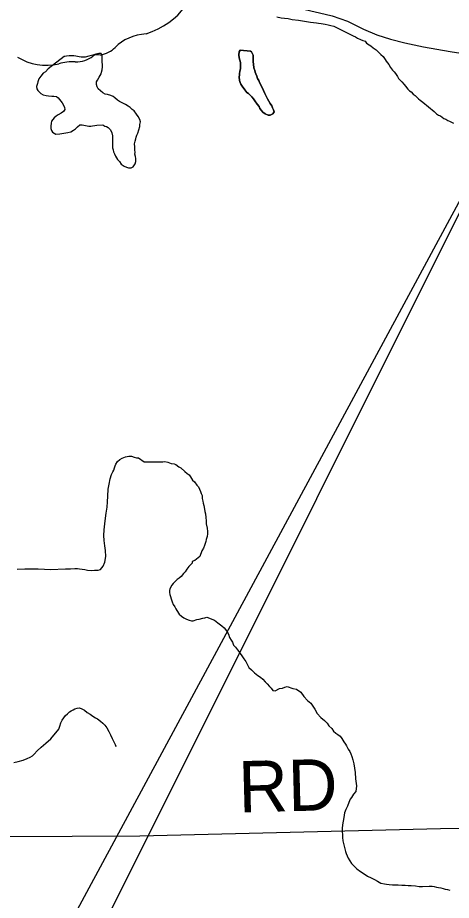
# Model space of a CAD drawing. Extents: x 0 to 34, y 0 to 22.
# Drawn here: x 6.066 to 6.547, y 16.147 to 17.124 of the extents above; entities that cross this region are included whole.
import ezdxf

# ---------------------------------------------------------------- set-up
doc = ezdxf.new("R2010")
doc.units = 0
for name, color, linetype in [('Default', 7, 'Continuous'), ('GM_X_Minor_Lake', 7, 'Continuous'), ('GM_X_Minor_River', 7, 'Continuous'), ('GM_X_State_Route', 7, 'Continuous'), ('GM_X_State_Shield', 7, 'Continuous'), ('GM_X_Township_Road', 7, 'Continuous'), ('GM_X_Township_Road_Text', 7, 'Continuous')]:
    doc.layers.add(name, color=color, linetype=linetype)

msp = doc.modelspace()

# ---------------------------------------------------------------- linework, layer by layer
at = {"layer": 'Default'}
msp.add_lwpolyline([(5.90994, 15.72564), (6.64074, 17.07843), (5.90994, 15.61811)], close=True, dxfattribs=at)
at = {"layer": 'GM_X_Minor_Lake'}
for points in [[(6.19735, 16.96793), (6.19699, 16.96984), (6.19626, 16.9725), (6.19629, 16.97441), (6.19594, 16.97745), (6.19598, 16.98049), (6.19564, 16.98392), (6.19644, 16.98695), (6.19723, 16.9896), (6.19763, 16.99149), (6.19842, 16.99339), (6.19958, 16.99565), (6.20157, 17.00323), (6.2016, 17.00551), (6.20239, 17.00816), (6.20167, 17.01083), (6.19981, 17.01428), (6.19794, 17.01696), (6.19532, 17.02041), (6.19306, 17.02196), (6.19081, 17.02427), (6.18854, 17.02581), (6.1859, 17.02737), (6.18363, 17.02853), (6.18137, 17.0297), (6.1791, 17.03087), (6.17684, 17.03242), (6.17382, 17.03473), (6.17194, 17.03627), (6.16968, 17.03744), (6.16589, 17.03863), (6.16323, 17.03904), (6.16058, 17.04021), (6.15795, 17.04252), (6.15532, 17.04484), (6.15421, 17.04713), (6.15347, 17.04942), (6.15351, 17.05246), (6.15467, 17.05434), (6.15662, 17.05774), (6.15778, 17.05963), (6.15894, 17.06152), (6.15934, 17.06341), (6.15975, 17.06569), (6.16017, 17.06911), (6.15989, 17.07671), (6.15992, 17.07937), (6.15994, 17.08165), (6.15883, 17.08395), (6.15617, 17.08398), (6.15274, 17.08326), (6.14968, 17.08215), (6.14511, 17.08107), (6.14092, 17.07998), (6.13673, 17.07965), (6.13446, 17.08005), (6.13256, 17.08046), (6.13066, 17.08086), (6.12839, 17.08127), (6.12649, 17.08129), (6.12345, 17.08133), (6.1204, 17.08098), (6.1185, 17.08062), (6.11774, 17.08063)], [(6.19735, 16.96793), (6.19699, 16.96984), (6.19626, 16.9725), (6.19629, 16.97441), (6.19594, 16.97745), (6.19598, 16.98049), (6.19564, 16.98392), (6.19644, 16.98695), (6.19723, 16.9896), (6.19763, 16.99149), (6.19842, 16.99339), (6.19958, 16.99565), (6.20157, 17.00323), (6.2016, 17.00551), (6.20239, 17.00816), (6.20167, 17.01083), (6.19981, 17.01428), (6.19794, 17.01696), (6.19532, 17.02041), (6.19306, 17.02196), (6.19081, 17.02427), (6.18854, 17.02581), (6.1859, 17.02737), (6.18363, 17.02853), (6.18137, 17.0297), (6.1791, 17.03087), (6.17684, 17.03242), (6.17382, 17.03473), (6.17194, 17.03627), (6.16968, 17.03744), (6.16589, 17.03863), (6.16323, 17.03904), (6.16058, 17.04021), (6.15795, 17.04252), (6.15532, 17.04484), (6.15421, 17.04713), (6.15347, 17.04942), (6.15351, 17.05246), (6.15467, 17.05434), (6.15662, 17.05774), (6.15778, 17.05963), (6.15894, 17.06152), (6.15934, 17.06341), (6.15975, 17.06569), (6.16017, 17.06911), (6.15989, 17.07671), (6.15992, 17.07937), (6.15994, 17.08165), (6.15883, 17.08395), (6.15617, 17.08398), (6.15274, 17.08326), (6.14968, 17.08215), (6.14511, 17.08107), (6.14092, 17.07998), (6.13673, 17.07965), (6.13446, 17.08005), (6.13256, 17.08046), (6.13066, 17.08086), (6.12839, 17.08127), (6.12649, 17.08129), (6.12345, 17.08133), (6.1204, 17.08098), (6.1185, 17.08062), (6.11774, 17.08063)], [(6.32428, 17.08648), (6.31277, 17.08764), (6.31161, 17.08575), (6.31122, 17.08233), (6.31163, 17.07912)], [(6.31163, 17.07912), (6.31122, 17.08233), (6.31161, 17.08575), (6.31277, 17.08764), (6.32428, 17.08648)], [(6.31163, 17.07912), (6.31308, 17.07395), (6.31306, 17.07129), (6.31304, 17.06748), (6.31226, 17.06406), (6.31187, 17.06178), (6.31186, 17.05988), (6.31147, 17.05798), (6.31183, 17.05418), (6.31258, 17.05189), (6.31333, 17.04998), (6.31484, 17.04769), (6.31787, 17.04387), (6.32014, 17.04081), (6.32204, 17.03966), (6.32393, 17.03774), (6.32583, 17.03583), (6.32734, 17.03391), (6.32885, 17.03162), (6.3315, 17.0278), (6.33377, 17.02512), (6.33452, 17.02322), (6.33604, 17.0213), (6.33793, 17.01901), (6.34059, 17.01709), (6.34363, 17.01555), (6.34591, 17.01553), (6.34897, 17.01703), (6.3505, 17.01931), (6.34975, 17.02159), (6.34862, 17.02388), (6.34787, 17.02617), (6.34598, 17.02847), (6.34447, 17.03114), (6.34296, 17.03381), (6.34145, 17.03686), (6.33994, 17.03954), (6.33844, 17.04297), (6.3358, 17.04907), (6.33429, 17.05175), (6.33354, 17.05403), (6.33203, 17.05632), (6.33128, 17.05899), (6.33015, 17.06128), (6.3294, 17.06319), (6.32903, 17.06509), (6.3279, 17.06814), (6.32754, 17.07195), (6.32717, 17.07461), (6.32719, 17.0769), (6.3272, 17.07918), (6.32722, 17.08222), (6.32533, 17.08566), (6.32428, 17.08648)], [(6.32428, 17.08648), (6.32533, 17.08566), (6.32722, 17.08222), (6.3272, 17.07918), (6.32719, 17.0769), (6.32717, 17.07461), (6.32754, 17.07195), (6.3279, 17.06814), (6.32903, 17.06509), (6.3294, 17.06319), (6.33015, 17.06128), (6.33128, 17.05899), (6.33203, 17.05632), (6.33354, 17.05403), (6.33429, 17.05175), (6.3358, 17.04907), (6.33844, 17.04297), (6.33994, 17.03954), (6.34145, 17.03686), (6.34296, 17.03381), (6.34447, 17.03114), (6.34598, 17.02847), (6.34787, 17.02617), (6.34862, 17.02388), (6.34975, 17.02159), (6.3505, 17.01931), (6.34897, 17.01703), (6.34591, 17.01553), (6.34363, 17.01555), (6.34059, 17.01709), (6.33793, 17.01901), (6.33604, 17.0213), (6.33452, 17.02322), (6.33377, 17.02512), (6.3315, 17.0278), (6.32885, 17.03162), (6.32734, 17.03391), (6.32583, 17.03583), (6.32393, 17.03774), (6.32204, 17.03966), (6.32014, 17.04081), (6.31787, 17.04387), (6.31484, 17.04769), (6.31333, 17.04998), (6.31258, 17.05189), (6.31183, 17.05418), (6.31147, 17.05798), (6.31186, 17.05988), (6.31187, 17.06178), (6.31226, 17.06406), (6.31304, 17.06748), (6.31306, 17.07129), (6.31308, 17.07395), (6.31163, 17.07912)], [(6.11774, 17.08063), (6.09993, 17.06698)], [(6.11774, 17.08063), (6.09993, 17.06698)], [(6.09993, 17.06698), (6.09701, 17.06377), (6.09471, 17.06228), (6.09201, 17.05889), (6.08969, 17.05588), (6.08851, 17.05247), (6.08811, 17.05057), (6.08731, 17.04754), (6.08765, 17.04488), (6.08877, 17.04296), (6.09215, 17.0395), (6.09442, 17.03834), (6.09783, 17.03754), (6.10049, 17.03712), (6.10428, 17.0367), (6.10656, 17.03667), (6.10922, 17.03626), (6.1111, 17.03472), (6.1141, 17.03126), (6.1156, 17.02934), (6.11709, 17.02666), (6.1182, 17.02399), (6.11855, 17.02208), (6.117, 17.01982), (6.11432, 17.01795), (6.11126, 17.01609), (6.10896, 17.01459), (6.10666, 17.01272), (6.10395, 17.00895), (6.10354, 17.00668), (6.10312, 17.00364), (6.10309, 17.00098), (6.10383, 16.99869), (6.10494, 16.99678), (6.10872, 16.99483), (6.11291, 16.99516), (6.11748, 16.99587), (6.12205, 16.99657), (6.1251, 16.9973), (6.12816, 16.99916), (6.13046, 17.00066), (6.13277, 17.00291), (6.13507, 17.00516), (6.13774, 17.00513), (6.13963, 17.00473), (6.14153, 17.00433), (6.14532, 17.00352), (6.14722, 17.0035), (6.14912, 17.00386), (6.15179, 17.0042), (6.15407, 17.00456), (6.16054, 17.00486), (6.16281, 17.00369), (6.1647, 17.00329), (6.16659, 17.00213), (6.16922, 16.99944), (6.1707, 16.996), (6.17142, 16.99295), (6.17139, 16.99067), (6.17136, 16.98762), (6.17132, 16.98496), (6.17129, 16.9823), (6.17126, 16.97964), (6.17199, 16.97736), (6.17235, 16.97507), (6.17346, 16.97277), (6.17457, 16.97048), (6.17569, 16.96857), (6.17681, 16.96665), (6.17906, 16.96434), (6.18093, 16.96166), (6.18432, 16.95934), (6.18697, 16.95817), (6.18924, 16.95738), (6.1919, 16.95735), (6.19419, 16.95846), (6.19652, 16.96186), (6.19731, 16.96451), (6.19735, 16.96793)], [(6.09993, 17.06698), (6.09701, 17.06377), (6.09471, 17.06228), (6.09201, 17.05889), (6.08969, 17.05588), (6.08851, 17.05247), (6.08811, 17.05057), (6.08731, 17.04754), (6.08765, 17.04488), (6.08877, 17.04296), (6.09215, 17.0395), (6.09442, 17.03834), (6.09783, 17.03754), (6.10049, 17.03712), (6.10428, 17.0367), (6.10656, 17.03667), (6.10922, 17.03626), (6.1111, 17.03472), (6.1141, 17.03126), (6.1156, 17.02934), (6.11709, 17.02666), (6.1182, 17.02399), (6.11855, 17.02208), (6.117, 17.01982), (6.11432, 17.01795), (6.11126, 17.01609), (6.10896, 17.01459), (6.10666, 17.01272), (6.10395, 17.00895), (6.10354, 17.00668), (6.10312, 17.00364), (6.10309, 17.00098), (6.10383, 16.99869), (6.10494, 16.99678), (6.10872, 16.99483), (6.11291, 16.99516), (6.11748, 16.99587), (6.12205, 16.99657), (6.1251, 16.9973), (6.12816, 16.99916), (6.13046, 17.00066), (6.13277, 17.00291), (6.13507, 17.00516), (6.13774, 17.00513), (6.13963, 17.00473), (6.14153, 17.00433), (6.14532, 17.00352), (6.14722, 17.0035), (6.14912, 17.00386), (6.15179, 17.0042), (6.15407, 17.00456), (6.16054, 17.00486), (6.16281, 17.00369), (6.1647, 17.00329), (6.16659, 17.00213), (6.16922, 16.99944), (6.1707, 16.996), (6.17142, 16.99295), (6.17139, 16.99067), (6.17136, 16.98762), (6.17132, 16.98496), (6.17129, 16.9823), (6.17126, 16.97964), (6.17199, 16.97736), (6.17235, 16.97507), (6.17346, 16.97277), (6.17457, 16.97048), (6.17569, 16.96857), (6.17681, 16.96665), (6.17906, 16.96434), (6.18093, 16.96166), (6.18432, 16.95934), (6.18697, 16.95817), (6.18924, 16.95738), (6.1919, 16.95735), (6.19419, 16.95846), (6.19652, 16.96186), (6.19731, 16.96451), (6.19735, 16.96793)]]:
    msp.add_lwpolyline(points, dxfattribs=at)
at = {"layer": 'GM_X_Minor_River'}
for points in [[(6.35334, 17.12427), (6.35829, 17.12347), (6.36171, 17.12307), (6.3659, 17.12266), (6.37047, 17.12149), (6.37732, 17.12068), (6.38417, 17.11949), (6.39064, 17.11869), (6.39407, 17.11828), (6.39711, 17.11788), (6.3994, 17.11749), (6.40244, 17.11709), (6.40473, 17.11669), (6.40701, 17.1163), (6.41005, 17.11552), (6.4131, 17.11473), (6.41652, 17.11395), (6.42906, 17.10778), (6.43362, 17.10547), (6.4378, 17.10354), (6.44046, 17.10238), (6.44274, 17.10084), (6.44616, 17.0993), (6.44844, 17.09814), (6.4511, 17.09736), (6.45261, 17.09545), (6.45565, 17.09353), (6.45755, 17.09237), (6.46021, 17.09007), (6.46324, 17.08777), (6.46514, 17.08624), (6.46855, 17.08279), (6.4712, 17.08049), (6.47347, 17.07743), (6.4746, 17.07552), (6.47725, 17.0717), (6.47914, 17.06827), (6.48141, 17.06559), (6.4833, 17.06367), (6.48482, 17.06176), (6.48708, 17.05832), (6.48822, 17.05641), (6.49011, 17.0545), (6.49163, 17.05259), (6.49428, 17.04952), (6.49579, 17.04761), (6.49844, 17.04455), (6.50034, 17.04264), (6.50223, 17.04148), (6.50451, 17.03881), (6.5064, 17.03727), (6.5083, 17.03574), (6.51019, 17.03382), (6.51209, 17.03229), (6.51512, 17.02999), (6.52119, 17.025), (6.52347, 17.02308), (6.52537, 17.02155), (6.52764, 17.01963), (6.5303, 17.01733), (6.53257, 17.0158), (6.53447, 17.01502), (6.53827, 17.01195), (6.54055, 17.01118), (6.54283, 17.00964), (6.54473, 17.00887)], [(6.54473, 17.00887), (6.54891, 17.00694)], [(6.17504, 16.62988), (6.17697, 16.63252), (6.17965, 16.63477), (6.18195, 16.63626), (6.18577, 16.63773), (6.18958, 16.63845), (6.19225, 16.63842), (6.19527, 16.63762), (6.19793, 16.63683), (6.20021, 16.6368), (6.20636, 16.6323)], [(6.06568, 16.51372), (6.07442, 16.51399), (6.08165, 16.51391), (6.08887, 16.51382), (6.09609, 16.51373), (6.10255, 16.51328), (6.11928, 16.51384), (6.12498, 16.51415), (6.12955, 16.51448), (6.13259, 16.51444), (6.13487, 16.51404), (6.1379, 16.51362), (6.14056, 16.51321), (6.14359, 16.51241), (6.14777, 16.51198), (6.15157, 16.51232), (6.15538, 16.51265), (6.15805, 16.51338), (6.16113, 16.51677), (6.1627, 16.52131), (6.16392, 16.52776), (6.16362, 16.53422), (6.16292, 16.53955), (6.16223, 16.54526), (6.16192, 16.55097), (6.16199, 16.55705), (6.16284, 16.56388), (6.16367, 16.56995), (6.1645, 16.57565), (6.16534, 16.5821), (6.16579, 16.58817), (6.16624, 16.59425), (6.16672, 16.60223), (6.16754, 16.60754), (6.16876, 16.61361), (6.17033, 16.61815), (6.17189, 16.62117), (6.17267, 16.62307), (6.17346, 16.62572), (6.17425, 16.62799), (6.17504, 16.62988)], [(6.20659, 16.63229), (6.21133, 16.63228), (6.21324, 16.63227), (6.21553, 16.63225), (6.21933, 16.63223), (6.22314, 16.6322), (6.22505, 16.63219), (6.22695, 16.63218), (6.22924, 16.63254), (6.23267, 16.63176), (6.23457, 16.63137), (6.23647, 16.63059), (6.23952, 16.63019), (6.24142, 16.62942), (6.24483, 16.62673), (6.24711, 16.62558), (6.25128, 16.62174), (6.25393, 16.61944), (6.25621, 16.61791), (6.25772, 16.61562), (6.25999, 16.61218), (6.26227, 16.61026), (6.26491, 16.60644), (6.26643, 16.60453), (6.26756, 16.60223), (6.26869, 16.59957), (6.26944, 16.59728), (6.27057, 16.59499), (6.27055, 16.59157), (6.2713, 16.5889), (6.27167, 16.58661), (6.27241, 16.58395), (6.27316, 16.58014), (6.27352, 16.57747), (6.27427, 16.57481), (6.27463, 16.57062), (6.27499, 16.56719), (6.27497, 16.56377), (6.27609, 16.55882), (6.27646, 16.55539), (6.27644, 16.55273), (6.27604, 16.54969), (6.27526, 16.54627), (6.27487, 16.54437), (6.2741, 16.5421), (6.27332, 16.53982), (6.27217, 16.53679), (6.27025, 16.53376), (6.26793, 16.52769), (6.26257, 16.52316), (6.25952, 16.52204), (6.25951, 16.52013), (6.25606, 16.51673), (6.25376, 16.51371), (6.25184, 16.51068), (6.24993, 16.50879), (6.24724, 16.50538), (6.24533, 16.50349), (6.24303, 16.50199), (6.24074, 16.5001), (6.23844, 16.49784), (6.23691, 16.49594), (6.23498, 16.49177), (6.23459, 16.48987), (6.23458, 16.48797), (6.23495, 16.48569), (6.2357, 16.4834), (6.23645, 16.48073), (6.23757, 16.4773), (6.2387, 16.47463), (6.24021, 16.47196), (6.24134, 16.46967), (6.24247, 16.46776), (6.24512, 16.46394), (6.24777, 16.46164), (6.25043, 16.45972), (6.25347, 16.45818), (6.25613, 16.45702), (6.25879, 16.45662), (6.2607, 16.45661), (6.2649, 16.4581), (6.26718, 16.45847), (6.27138, 16.45958), (6.27367, 16.45994), (6.27596, 16.46069), (6.28432, 16.45721), (6.28811, 16.45414), (6.29229, 16.45107), (6.29494, 16.44877), (6.29646, 16.44686), (6.29835, 16.44418), (6.29986, 16.44189), (6.30098, 16.43808), (6.30287, 16.43502), (6.30438, 16.43273), (6.30551, 16.42968), (6.3074, 16.42738), (6.30967, 16.42433), (6.31119, 16.42242)], [(6.31119, 16.42242), (6.3127, 16.4205), (6.31459, 16.41783), (6.31686, 16.41439), (6.31913, 16.41133), (6.32101, 16.4079), (6.32252, 16.40484), (6.32518, 16.40216), (6.32859, 16.3991), (6.33238, 16.39603), (6.33542, 16.39411), (6.33769, 16.39181), (6.34034, 16.38913), (6.34262, 16.38683), (6.34527, 16.38377), (6.34716, 16.38186), (6.34905, 16.37956), (6.35134, 16.37916), (6.3563, 16.3818), (6.35973, 16.38215), (6.36203, 16.38328), (6.3647, 16.38402), (6.37116, 16.38169), (6.37497, 16.38091), (6.3799, 16.37745), (6.3833, 16.37286), (6.38747, 16.36827), (6.39089, 16.36559), (6.39315, 16.36215), (6.39542, 16.35871), (6.39806, 16.35413), (6.40223, 16.34953), (6.40602, 16.34609), (6.40905, 16.3434), (6.41094, 16.34035), (6.41436, 16.33728), (6.41625, 16.33461), (6.41852, 16.33231), (6.4208, 16.33077), (6.42345, 16.32885), (6.42534, 16.32618), (6.42761, 16.32274), (6.4295, 16.32006), (6.43064, 16.31816), (6.43252, 16.31472), (6.43403, 16.31205), (6.43516, 16.30938), (6.43629, 16.30633), (6.43741, 16.3029), (6.43853, 16.29832), (6.43927, 16.29337), (6.44, 16.2888), (6.44035, 16.28158), (6.44108, 16.27662), (6.44145, 16.27396), (6.44066, 16.26788), (6.43836, 16.26485), (6.4372, 16.26296), (6.43605, 16.26107), (6.43452, 16.25917), (6.43297, 16.25538), (6.43143, 16.25159), (6.42989, 16.2478), (6.42834, 16.244), (6.42755, 16.23906), (6.42677, 16.23488), (6.42599, 16.2307), (6.42559, 16.2269), (6.42557, 16.2231), (6.42593, 16.22005), (6.42591, 16.21701), (6.42628, 16.21321), (6.42702, 16.21016), (6.42777, 16.20711), (6.42852, 16.20444), (6.42926, 16.2014), (6.43001, 16.19911), (6.43114, 16.19644), (6.43227, 16.19415), (6.43416, 16.19109), (6.43605, 16.18804), (6.43832, 16.18574), (6.44211, 16.18229), (6.44591, 16.17922), (6.45008, 16.17653), (6.45388, 16.17423), (6.45768, 16.1723), (6.46148, 16.17037), (6.4649, 16.16844), (6.4687, 16.16652), (6.4725, 16.16573), (6.47479, 16.16534), (6.47783, 16.16493), (6.48126, 16.16453), (6.48773, 16.16449), (6.49192, 16.16408), (6.49535, 16.16405), (6.49878, 16.16365), (6.5022, 16.16363), (6.50677, 16.16322), (6.51096, 16.16281)], [(6.08028, 16.30561), (6.08258, 16.30711), (6.0845, 16.30898), (6.08797, 16.31274), (6.0922, 16.31687), (6.09757, 16.32099), (6.10295, 16.32587), (6.11183, 16.33679), (6.113, 16.33982), (6.11419, 16.3436), (6.11575, 16.34662), (6.1173, 16.34927), (6.11923, 16.35191), (6.12154, 16.35378), (6.12384, 16.35565), (6.12575, 16.35677), (6.12767, 16.35789), (6.12958, 16.35901), (6.13225, 16.35973), (6.13492, 16.36008), (6.13757, 16.35929), (6.14021, 16.35774), (6.14322, 16.35504), (6.14662, 16.3531), (6.14963, 16.35117), (6.15265, 16.34923), (6.15492, 16.34806), (6.15793, 16.34537), (6.16056, 16.34343), (6.16282, 16.34112), (6.16506, 16.33806), (6.16729, 16.33423), (6.16915, 16.33041), (6.171, 16.3262), (6.17286, 16.32276), (6.17434, 16.3197), (6.17508, 16.31779), (6.17508, 16.31741), (6.17508, 16.31779)], [(6.06197, 16.29975), (6.06692, 16.30083), (6.07226, 16.30229), (6.07684, 16.30413), (6.08028, 16.30561)], [(6.51096, 16.16281), (6.51477, 16.16279), (6.52201, 16.16312), (6.52544, 16.16309), (6.52772, 16.1627), (6.53, 16.16192), (6.53229, 16.16153), (6.53495, 16.16113), (6.53761, 16.16035), (6.53989, 16.15957), (6.54218, 16.15918), (6.54484, 16.15878), (6.54484, 16.15878)]]:
    msp.add_lwpolyline(points, dxfattribs=at)
at = {"layer": 'GM_X_State_Route'}
msp.add_lwpolyline([(6.36004, 17.1383), (6.363, 17.1377), (6.38001, 17.13374), (6.40072, 17.12892), (6.41476, 17.12541), (6.43143, 17.11949), (6.44919, 17.11094), (6.46411, 17.10458), (6.47924, 17.09975), (6.49525, 17.09581), (6.51565, 17.0912), (6.54526, 17.08615), (6.57355, 17.08177), (6.60974, 17.07914), (6.81306, 17.07453), (6.92886, 17.07212), (7.14841, 17.07014), (7.55702, 17.06334), (7.97321, 17.05777)], dxfattribs=at)
at = {"layer": 'GM_X_State_Shield'}
for centre, major_axis, start_param, end_param in [((6.17539, 17.17024), (0.08742, 0), 5.101752, 6.440018), ((6.21225, 17.06735), (0.04788, 0), 1.647645, 2.488434), ((6.15159, 17.10414), (0.02824, 0), 4.937069, 5.64225), ((6.09803, 17.111), (0.05011, 0), 4.026481, 4.996735), ((6.12698, 17.04181), (0.04118, 0), 1.495662, 1.94098), ((6.13064, 17.09601), (0.0267, 0), 4.691044, 5.507374), ((6.1548, 17.07663), (0.00752, 0), 1.147584, 2.315152)]:
    msp.add_ellipse(centre, major_axis=major_axis, ratio=0.8, start_param=start_param, end_param=end_param, dxfattribs=at)
at = {"layer": 'GM_X_Township_Road'}
msp.add_lwpolyline([(5.6017, 16.17213), (5.70149, 16.19218), (5.70871, 16.1967), (5.71291, 16.202), (5.716, 16.21489), (5.71907, 16.22248), (5.7263, 16.22814), (5.73351, 16.23039), (5.74412, 16.2292), (5.76417, 16.22075), (5.77384, 16.21773), (5.78538, 16.21572), (5.97606, 16.21751), (6.20162, 16.21877), (6.53442, 16.22672), (6.93852, 16.22879)], dxfattribs=at)

# ---------------------------------------------------------------- texts
at = {"layer": 'GM_X_Township_Road_Text'}
msp.add_text('RD', height=0.056818, rotation=1.48246, dxfattribs=at).set_placement((6.31145, 16.24442))

doc.saveas('drawing.dxf')
